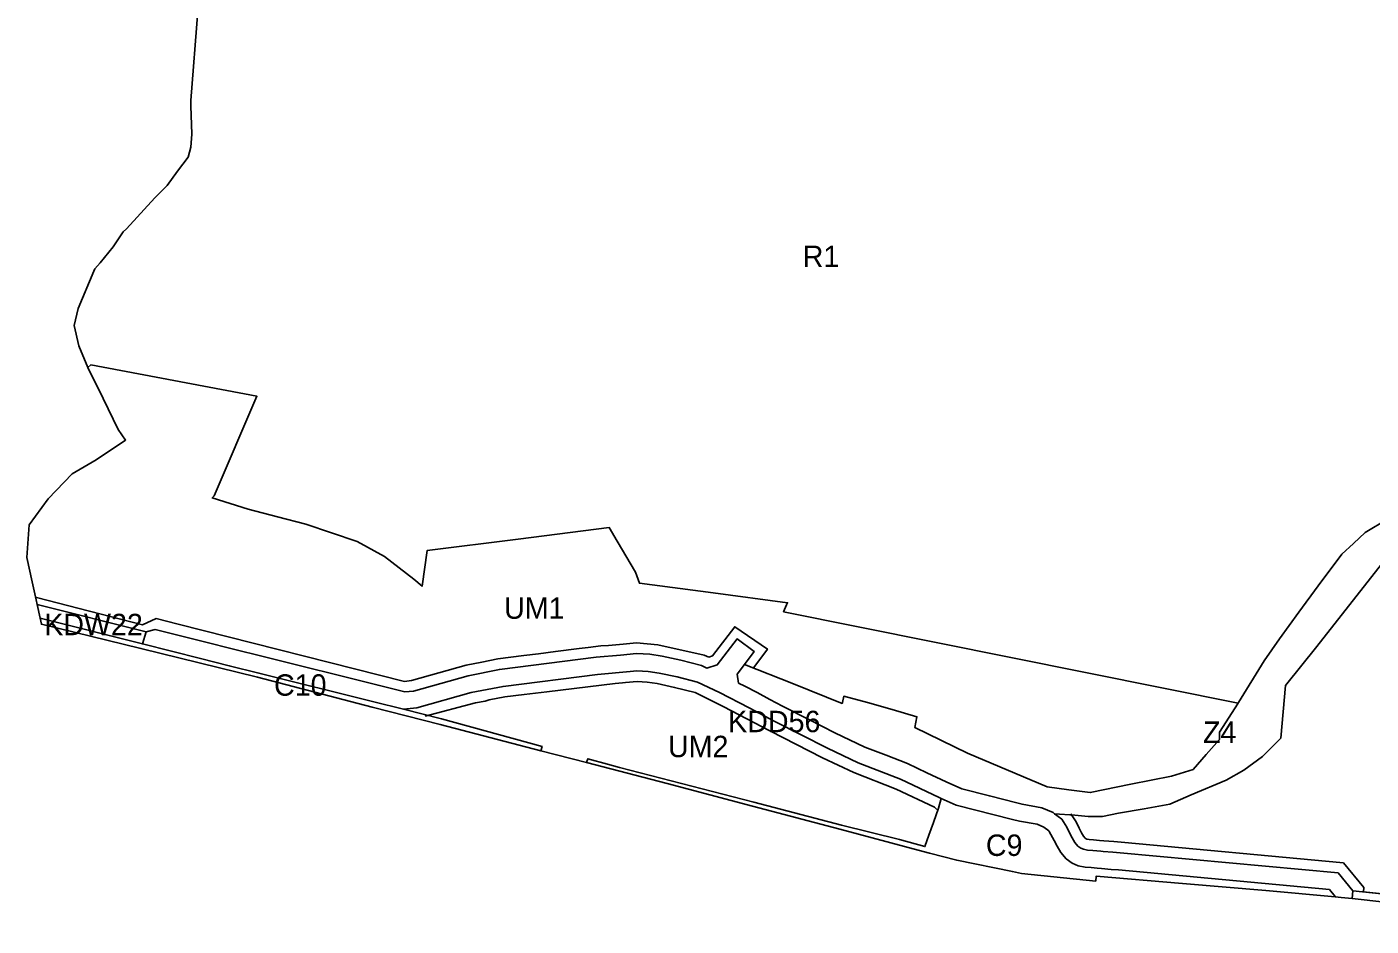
# Model space of a CAD drawing. Extents: x 7428841 to 7433518, y 5545054 to 5546840.
# Drawn here: x 7428886 to 7429514, y 5545126 to 5545546 of the extents above; entities that cross this region are included whole.
import ezdxf

# ---------------------------------------------------------------- set-up
doc = ezdxf.new("R2010")
doc.units = 0
for name, color, linetype in [('linie_rozgraniczajace', 7, 'Continuous'), ('linie_zabudowy_nieprzekraczalne', 7, 'Continuous'), ('oznaczenia_przeznaczen', 7, 'Continuous')]:
    doc.layers.add(name, color=color, linetype=linetype)

msp = doc.modelspace()

# ---------------------------------------------------------------- linework, layer by layer
at = {"layer": 'linie_rozgraniczajace'}
for points in [[(7428908.6, 5545406.67), (7428910.45, 5545414.55), (7428917.68, 5545431.98), (7428918.16, 5545433.14), (7428920.67, 5545435.86), (7428926.7, 5545443.37), (7428931.41, 5545450.29), (7428932.94, 5545451.83), (7428946.26, 5545466.29), (7428951.91, 5545472.06), (7428956.85, 5545478.66), (7428961.79, 5545485.27), (7428963.04, 5545489.85), (7428963.43, 5545495.97), (7428962.99, 5545509.2), (7428963.09, 5545511.74), (7428966.37, 5545553.5)], [(7429040.66, 5545305.71), (7429028.75, 5545309.84), (7429016.69, 5545313.86), (7429003.5, 5545317.24), (7428989.75, 5545320.83), (7428973.04, 5545326.06), (7428973.95, 5545327.1), (7428993.93, 5545373.61), (7428955.13, 5545380.91), (7428916.32, 5545388.22), (7428914.97, 5545387.07), (7428910.71, 5545397.19), (7428908.6, 5545406.67)], [(7429522.06, 5545316.24), (7429511.53, 5545309.92), (7429506.09, 5545304.84), (7429500.65, 5545299.76), (7429489.56, 5545285.04), (7429480.52, 5545272.67), (7429471.47, 5545260.31), (7429464.46, 5545250.02), (7429452.37, 5545230.49), (7429452.19, 5545230.2), (7429239.91, 5545272.96), (7429241.31, 5545276.11), (7429241.76, 5545277.1), (7429207.03, 5545281.68), (7429172.58, 5545286.22), (7429170.79, 5545291.4), (7429162.1, 5545305.84), (7429158.45, 5545312.21), (7429115.97, 5545306.89), (7429073.49, 5545301.57), (7429071.06, 5545284.85), (7429067.14, 5545288.13), (7429053.52, 5545298.71), (7429040.66, 5545305.71)], [(7429529.42, 5545308.25), (7429489, 5545256.77), (7429474.33, 5545238.5), (7429472.14, 5545213.83), (7429463.54, 5545205.26), (7429454.93, 5545198.9), (7429446.71, 5545194.22), (7429430.35, 5545187.38), (7429420.37, 5545183.08), (7429408.36, 5545180.94), (7429396.35, 5545178.81), (7429388.84, 5545177.35), (7429382.49, 5545177.35), (7429382.37, 5545177.35), (7429382.25, 5545177.36), (7429375.93, 5545177.85), (7429366.49, 5545178.58), (7429365.76, 5545179.14), (7429360.6, 5545181.3), (7429351.34, 5545182.98), (7429348.84, 5545183.62), (7429336.02, 5545186.89), (7429323.21, 5545190.16), (7429315.89, 5545193.41), (7429306.81, 5545197.74), (7429297.72, 5545202.07), (7429287.8, 5545205.91), (7429277.88, 5545209.75), (7429263.89, 5545216.4), (7429251.67, 5545222.58), (7429239.46, 5545228.75), (7429233.54, 5545231.96), (7429227.62, 5545235.16), (7429221.84, 5545238.11), (7429218.9, 5545239.61), (7429218.18, 5545243.83), (7429221.6, 5545248.28), (7429244.48, 5545239.18), (7429267.24, 5545230.12), (7429267.36, 5545230.58), (7429268.05, 5545233.43), (7429279.07, 5545230.56), (7429290.69, 5545227.22), (7429302.2, 5545223.91), (7429301.17, 5545218.88), (7429325.74, 5545206.85), (7429363, 5545191.11), (7429373.07, 5545189.78), (7429383.14, 5545188.44), (7429402.11, 5545192.32), (7429421.08, 5545196.19), (7429431.17, 5545199.3), (7429437.34, 5545206.29), (7429443.52, 5545213.28), (7429443.47, 5545216.67), (7429452.19, 5545230.2), (7429452.37, 5545230.49), (7429464.46, 5545250.02), (7429471.47, 5545260.31), (7429480.52, 5545272.67), (7429489.56, 5545285.04), (7429500.65, 5545299.76), (7429506.09, 5545304.84), (7429511.53, 5545309.92), (7429522.06, 5545316.24)], [(7429535.89, 5545139.5), (7429505.84, 5545142.57), (7429498.89, 5545150.92), (7429397.08, 5545160.28), (7429393.66, 5545160.57), (7429389.11, 5545160.98), (7429388.09, 5545161.07), (7429384.28, 5545161.4), (7429381.94, 5545161.6), (7429379.99, 5545161.98), (7429378.73, 5545162.55), (7429377.35, 5545163.51), (7429375.95, 5545165.16), (7429374.67, 5545167.28), (7429373.5, 5545169.69), (7429372.2, 5545172.32), (7429369.82, 5545176.03), (7429366.49, 5545178.58), (7429375.93, 5545177.85), (7429382.25, 5545177.36), (7429382.37, 5545177.35), (7429382.49, 5545177.35), (7429388.84, 5545177.35), (7429396.35, 5545178.81), (7429408.36, 5545180.94), (7429420.37, 5545183.08), (7429430.35, 5545187.38), (7429446.71, 5545194.22), (7429454.93, 5545198.9), (7429463.54, 5545205.26), (7429472.14, 5545213.83), (7429474.33, 5545238.5), (7429489, 5545256.77), (7429529.42, 5545308.25)], [(7428940.43, 5545257.89), (7428942.24, 5545263.62), (7428946.34, 5545264.66), (7428969.43, 5545258.87), (7428982.92, 5545255.5), (7428996.79, 5545252.03), (7429050.47, 5545238.59), (7429063, 5545235.46), (7429067.06, 5545235.89), (7429092.56, 5545243.07), (7429107.2, 5545245.99), (7429152.33, 5545251.67), (7429163.67, 5545252.67), (7429171.23, 5545253.37), (7429177.51, 5545253.04), (7429183.25, 5545252.15), (7429191.97, 5545250.24), (7429201.5, 5545247.84), (7429204.07, 5545246.58), (7429208.92, 5545248.19), (7429218.18, 5545260.24), (7429226.24, 5545254.32), (7429221.6, 5545248.28), (7429218.18, 5545243.83), (7429218.9, 5545239.61), (7429221.84, 5545238.11), (7429227.62, 5545235.16), (7429233.54, 5545231.96), (7429239.46, 5545228.75), (7429251.67, 5545222.58), (7429263.89, 5545216.4), (7429277.88, 5545209.75), (7429287.8, 5545205.91), (7429297.72, 5545202.07), (7429306.81, 5545197.74), (7429315.89, 5545193.41), (7429323.21, 5545190.16), (7429336.02, 5545186.89), (7429348.84, 5545183.62), (7429351.34, 5545182.98), (7429360.6, 5545181.3), (7429365.76, 5545179.14), (7429366.49, 5545178.58), (7429369.82, 5545176.03), (7429372.2, 5545172.32), (7429373.5, 5545169.69), (7429374.67, 5545167.28), (7429375.95, 5545165.16), (7429377.35, 5545163.51), (7429378.73, 5545162.55), (7429379.99, 5545161.98), (7429381.94, 5545161.6), (7429384.28, 5545161.4), (7429388.09, 5545161.07), (7429389.11, 5545160.98), (7429393.66, 5545160.57), (7429397.08, 5545160.28), (7429498.89, 5545150.92), (7429505.84, 5545142.57), (7429505.51, 5545138.97), (7429500.4, 5545139.54), (7429497.55, 5545139.8), (7429497.57, 5545140), (7429494.86, 5545143.26), (7429396.37, 5545152.31), (7429392.97, 5545152.6), (7429388.4, 5545153.01), (7429386.36, 5545153.19), (7429383.58, 5545153.43), (7429380.83, 5545153.67), (7429377.54, 5545154.31), (7429374.77, 5545155.57), (7429371.93, 5545157.53), (7429369.43, 5545160.48), (7429367.64, 5545163.46), (7429366.32, 5545166.16), (7429363.99, 5545170.3), (7429363.84, 5545170.53), (7429361.51, 5545172.32), (7429358.32, 5545173.7), (7429350.13, 5545175.15), (7429346.86, 5545175.87), (7429320.58, 5545182.58), (7429313.57, 5545185.69), (7429312.65, 5545186.1), (7429294.56, 5545194.72), (7429274.71, 5545202.4), (7429260.37, 5545209.21), (7429235.75, 5545221.67), (7429223.9, 5545228.08), (7429210.04, 5545235.15), (7429199.76, 5545240.03), (7429190.14, 5545242.45), (7429181.78, 5545244.28), (7429176.68, 5545245.07), (7429171.38, 5545245.35), (7429168.32, 5545245.07), (7429153, 5545243.66), (7429108.89, 5545238.08), (7429093.96, 5545235.16)], [(7429093.96, 5545235.16), (7429068.58, 5545228.01), (7429062.44, 5545227.35), (7429048.53, 5545230.83), (7428994.85, 5545244.27), (7428980.98, 5545247.74), (7428967.48, 5545251.11), (7428940.43, 5545257.89)]]:
    msp.add_lwpolyline(points, dxfattribs=at)
for points in [[(7428886.46, 5545298.28), (7428887.51, 5545313.47), (7428896.36, 5545325.73), (7428907.56, 5545337.38), (7428918.79, 5545343.88), (7428932.55, 5545353.12), (7428929.1, 5545358.03), (7428922.04, 5545372.55), (7428914.97, 5545387.07), (7428916.32, 5545388.22), (7428955.13, 5545380.91), (7428993.93, 5545373.61), (7428973.95, 5545327.1), (7428973.04, 5545326.06), (7428989.75, 5545320.83), (7429003.5, 5545317.24), (7429016.69, 5545313.86), (7429028.75, 5545309.84), (7429040.66, 5545305.71), (7429053.52, 5545298.71), (7429067.14, 5545288.13), (7429071.06, 5545284.85), (7429073.49, 5545301.57), (7429115.97, 5545306.89), (7429158.45, 5545312.21), (7429162.1, 5545305.84), (7429170.79, 5545291.4), (7429172.58, 5545286.22), (7429207.03, 5545281.68), (7429241.76, 5545277.1), (7429241.31, 5545276.11), (7429239.91, 5545272.96), (7429452.19, 5545230.2), (7429443.47, 5545216.67), (7429443.52, 5545213.28), (7429437.34, 5545206.29), (7429431.17, 5545199.3), (7429421.08, 5545196.19), (7429402.11, 5545192.32), (7429383.14, 5545188.44), (7429373.07, 5545189.78), (7429363, 5545191.11), (7429325.74, 5545206.85), (7429301.17, 5545218.88), (7429302.2, 5545223.91), (7429290.69, 5545227.22), (7429279.07, 5545230.56), (7429268.05, 5545233.43), (7429267.36, 5545230.58), (7429267.24, 5545230.12), (7429244.48, 5545239.18), (7429221.6, 5545248.28), (7429226.24, 5545254.32), (7429218.18, 5545260.24), (7429208.92, 5545248.19), (7429204.07, 5545246.58), (7429201.5, 5545247.84), (7429191.97, 5545250.24), (7429183.25, 5545252.15), (7429177.51, 5545253.04), (7429171.23, 5545253.37), (7429163.67, 5545252.67), (7429152.33, 5545251.67), (7429107.2, 5545245.99), (7429092.56, 5545243.07), (7429067.06, 5545235.89), (7429063, 5545235.46), (7429050.47, 5545238.59), (7428996.79, 5545252.03), (7428982.92, 5545255.5), (7428969.43, 5545258.87), (7428946.34, 5545264.66), (7428942.24, 5545263.62), (7428891.23, 5545276.38), (7428890.76, 5545278.56), (7428888.97, 5545286.9)], [(7428891.23, 5545276.38), (7428942.24, 5545263.62), (7428940.43, 5545257.89), (7428892.64, 5545269.85)], [(7428892.64, 5545269.85), (7428940.43, 5545257.89), (7428967.48, 5545251.11), (7428980.98, 5545247.74), (7428994.85, 5545244.27), (7429048.53, 5545230.83), (7429062.44, 5545227.35), (7429080.2, 5545222.9), (7429127.07, 5545209.95), (7429126.48, 5545208.03), (7429079.46, 5545220.28), (7429047.73, 5545228.37), (7428994.24, 5545242.32), (7428939.74, 5545255.79), (7428893.23, 5545267.11)], [(7429062.44, 5545227.35), (7429068.58, 5545228.01), (7429093.96, 5545235.16), (7429108.89, 5545238.08), (7429153, 5545243.66), (7429168.32, 5545245.07), (7429171.38, 5545245.35), (7429176.68, 5545245.07), (7429181.78, 5545244.28), (7429190.14, 5545242.45), (7429199.76, 5545240.03), (7429210.04, 5545235.15), (7429223.9, 5545228.08), (7429235.75, 5545221.67), (7429260.37, 5545209.21), (7429274.71, 5545202.4), (7429294.56, 5545194.72), (7429312.65, 5545186.1), (7429313.57, 5545185.69), (7429312.23, 5545181.26), (7429309.89, 5545174.47), (7429307.82, 5545168.57), (7429305.93, 5545163.22), (7429294.02, 5545166.49), (7429266.92, 5545173.18), (7429225.98, 5545184.01), (7429163.25, 5545200.23), (7429157.59, 5545201.77), (7429148.45, 5545204.26), (7429147.92, 5545202.46), (7429126.48, 5545208.03), (7429127.07, 5545209.95), (7429080.2, 5545222.9)], [(7429147.92, 5545202.46), (7429148.45, 5545204.26), (7429157.59, 5545201.77), (7429163.25, 5545200.23), (7429225.98, 5545184.01), (7429266.92, 5545173.18), (7429294.02, 5545166.49), (7429305.93, 5545163.22), (7429307.82, 5545168.57), (7429309.89, 5545174.47), (7429312.23, 5545181.26), (7429313.57, 5545185.69), (7429320.58, 5545182.58), (7429346.86, 5545175.87), (7429350.13, 5545175.15), (7429358.32, 5545173.7), (7429361.51, 5545172.32), (7429363.84, 5545170.53), (7429363.99, 5545170.3), (7429366.32, 5545166.16), (7429367.64, 5545163.46), (7429369.43, 5545160.48), (7429371.93, 5545157.53), (7429374.77, 5545155.57), (7429377.54, 5545154.31), (7429380.83, 5545153.67), (7429383.58, 5545153.43), (7429386.36, 5545153.19), (7429388.4, 5545153.01), (7429392.97, 5545152.6), (7429396.37, 5545152.31), (7429494.86, 5545143.26), (7429497.57, 5545140), (7429497.55, 5545139.8), (7429465.2, 5545142.69), (7429426.25, 5545146.06), (7429385.96, 5545149.48), (7429385.71, 5545147.15), (7429350.97, 5545150.72), (7429346.77, 5545151.57), (7429320.81, 5545156.84), (7429308.07, 5545160.22), (7429305.16, 5545160.99), (7429266.15, 5545171.35), (7429225.4, 5545182.16), (7429185.47, 5545192.72)], [(7429505.51, 5545138.97), (7429505.84, 5545142.57), (7429535.89, 5545139.5), (7429570.76, 5545135.84), (7429604.96, 5545130.73), (7429604.42, 5545126.1), (7429569.55, 5545128.79), (7429569.99, 5545133.5), (7429549.13, 5545135.14), (7429535.93, 5545135.57)]]:
    msp.add_lwpolyline(points, close=True, dxfattribs=at)
at = {"layer": 'linie_zabudowy_nieprzekraczalne'}
for points in [[(7428891, 5545279.53), (7428940.47, 5545266.85), (7428946.83, 5545269.7)], [(7428946.83, 5545269.7), (7428957.11, 5545267.11), (7429062.82, 5545240.4)], [(7429205.03, 5545251.64), (7429206.76, 5545252.32), (7429217.06, 5545265.94), (7429232.39, 5545255.46), (7429225.97, 5545246.9)], [(7429106.43, 5545250.94), (7429118.51, 5545252.46), (7429125.46, 5545253.23), (7429133.45, 5545254.28), (7429144.44, 5545255.78), (7429148.64, 5545256.28), (7429154.57, 5545257.03), (7429158.16, 5545257.2), (7429164.96, 5545257.76), (7429171.14, 5545258.38), (7429181.1, 5545257.54), (7429202.79, 5545252.67), (7429205.03, 5545251.64)], [(7429062.82, 5545240.4), (7429066.11, 5545240.82), (7429091.62, 5545248), (7429098.97, 5545249.45), (7429106.36, 5545250.93)], [(7429198.54, 5545235.18), (7429189, 5545237.58), (7429180.86, 5545239.36), (7429176.17, 5545240.09), (7429171.48, 5545240.34), (7429166.13, 5545239.85), (7429164.65, 5545239.73), (7429161.17, 5545239.39), (7429129.28, 5545235.57), (7429118.7, 5545234.29), (7429109.69, 5545233.14), (7429102.36, 5545231.71), (7429100.55, 5545231.19)], [(7429100.47, 5545231.17), (7429096.06, 5545230.31), (7429072.5, 5545224.09)], [(7429311.55, 5545180.53), (7429310.35, 5545181.65), (7429292.57, 5545190.12), (7429272.74, 5545197.8), (7429258.16, 5545204.72), (7429233.44, 5545217.23), (7429211.64, 5545228.72), (7429198.55, 5545235.22)], [(7429374.11, 5545178.6), (7429376.56, 5545174.78), (7429377.98, 5545171.89), (7429379.07, 5545169.68), (7429380.02, 5545168.09), (7429380.74, 5545167.25), (7429381.21, 5545166.92), (7429381.52, 5545166.78), (7429382.64, 5545166.56), (7429384.72, 5545166.38), (7429387.51, 5545166.13), (7429389.55, 5545165.96), (7429394.1, 5545165.55), (7429397.52, 5545165.26), (7429501.41, 5545155.71), (7429511.01, 5545144.17), (7429510.81, 5545142.04)], [(7429510.81, 5545142.04), (7429535.89, 5545139.5), (7429570.76, 5545135.84), (7429593.38, 5545133.47), (7429658.51, 5545127.18), (7429660.52, 5545132.36), (7429662.59, 5545153.5), (7429662.75, 5545155.06), (7429677.51, 5545153.62)]]:
    msp.add_lwpolyline(points, dxfattribs=at)

# ---------------------------------------------------------------- texts
at = {"layer": 'oznaczenia_przeznaczen'}
for s, p in [('R1', (7429248.85, 5545433.91)), ('UM1', (7429109.36, 5545269.63)), ('KDW22', (7428894.55, 5545261.97)), ('C10', (7429001.9, 5545233.7)), ('KDD56', (7429214, 5545216.67)), ('Z4', (7429435.81, 5545211.67)), ('UM2', (7429185.93, 5545205)), ('C9', (7429334.4, 5545158.88))]:
    msp.add_text(s, height=10, dxfattribs=at).set_placement(p)

doc.saveas('drawing.dxf')
